// Mitsubishi GX Works2 project: 22.2种产品分别延时自断（比较指令）   PLC: FX3U/FX3UC

PROGRAM MAIN
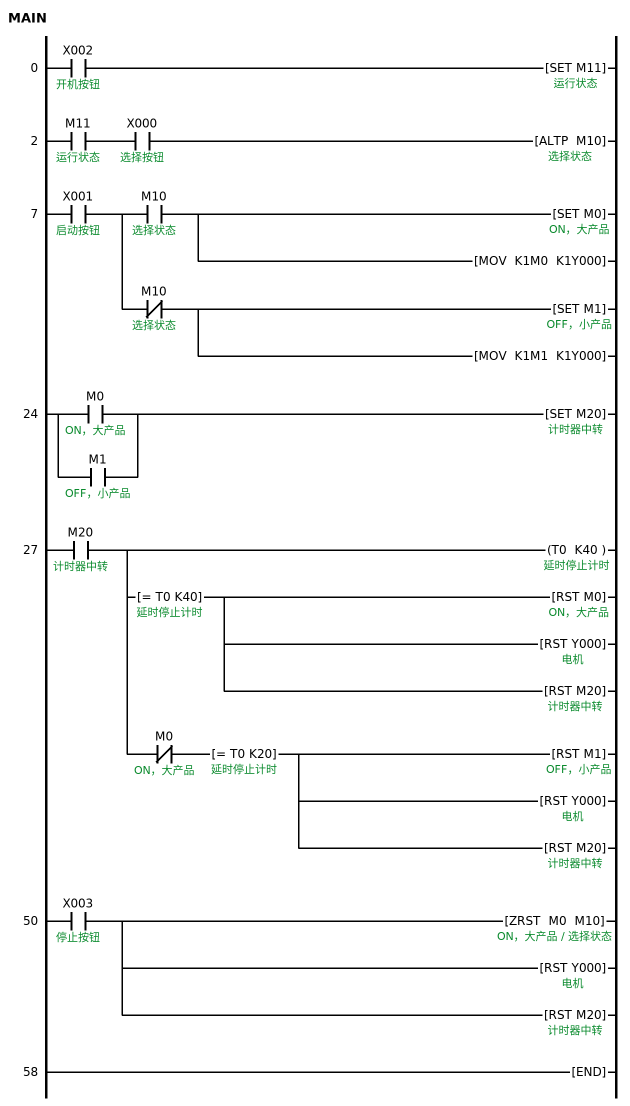
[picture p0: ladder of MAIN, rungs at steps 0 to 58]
0     LD      X002  ; 开机按钮
      SET     M11  ; 运行状态
2     LD      M11  ; 运行状态
      AND     X000  ; 选择按钮
      ALTP    M10  ; 选择状态
7     LD      X001  ; 启动按钮
      MPS
      AND     M10  ; 选择状态
      SET     M0  ; ON，大产品
      MOV     K1M0 K1Y000  ; 电机
      MPP
      ANI     M10  ; 选择状态
      SET     M1  ; OFF，小产品
      MOV     K1M1 K1Y000
24    LD      M0  ; ON，大产品
      OR      M1  ; OFF，小产品
      SET     M20  ; 计时器中转
27    LD      M20  ; 计时器中转
      OUT     T0 K40  ; 延时停止计时
      MPS
      AND=    T0 K40  ; 延时停止计时
      RST     M0  ; ON，大产品
      RST     Y000  ; 电机
      RST     M20  ; 计时器中转
      MPP
      ANI     M0  ; ON，大产品
      AND=    T0 K20  ; 延时停止计时
      RST     M1  ; OFF，小产品
      RST     Y000  ; 电机
      RST     M20  ; 计时器中转
50    LD      X003  ; 停止按钮
      ZRST    M0 M10
      RST     Y000  ; 电机
      RST     M20  ; 计时器中转
58    END
END_PROGRAM

// device comments not shown above
M2  ; 选择状态
M21  ; 2秒计时器中转
T1  ; 延时2秒停止
D0  ; 选择ON状态
D1  ; 选择OFF状态
